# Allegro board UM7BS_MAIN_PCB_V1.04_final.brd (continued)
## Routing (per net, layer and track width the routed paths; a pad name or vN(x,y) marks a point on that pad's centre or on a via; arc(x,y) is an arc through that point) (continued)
GND_EARTH:
  vias: v1(81,12.24) v1(82.24,13.21) v1(83.39,14.42) v1(86.83,14.37) v1(89.73,14.75) v1(91.16,18.72) v1(91.16,16.16) v1(93.09,30.7) v1(94.33,18.52) v1(97.19,30.48) v1(97.26,25.74) v1(97.87,30.48) v1(97.92,22.71) v1(97.89,19.92) v1(98.06,17.3) v1(99.57,21.39) v1(100.41,41.04) v1(100.39,38.61) v1(100.44,36.29) v1(100.49,33.51) v2(81.7,22.25) v2(81.7,21.36) v2(81.7,20.47) v2(96.48,30.22) v2(96.48,28.66)
PGNDSNS1: length 13.7
  TOP w0.203: U11.36 165.7,20.39 v1(165.74,20.35)
  TOP w0.254: R837.1 175.15,24.09 174.46,23.4 173.95,23.4 v1(173.67,23.68)
  LAY4 w0.254: v1(173.67,23.68) 173.53,23.82 171.07,23.82 170.4,24.49 168.7,24.49 165.74,21.53 v1(165.74,20.35)
PGNDSNS6: length 37.1
  TOP w0.178: v1(164.29,21.99) 164.29,21.99 U11.40
  LAY3 w0.305: v1(192.83,23.21) 190.62,23.21 189.83,22.42 172.98,22.42 170.5,24.9 168.27,24.9 165.86,22.48 164.79,22.48 v1(164.29,21.99)
  BOTTOM w0.508: v1(192.83,23.21) 194.65,23.21 196.72,21.14 R838.1
V1P24A_PWRGD: length 43
  LAY4 w0.102: v1(157.89,51.28) 158.26,51.65 164.04,51.65 165.99,49.7 169.38,49.7 170.09,48.99 170.09,44.95 165.6,40.45 163,40.45 162.2,39.66 162.2,32.45 v1(163.06,31.59)
  BOTTOM w0.102: v1(163.06,31.59) 163.43,31.21 R559.2 ; R3105.2 155.12,50.38 155.58,50.83 157.44,50.83 v1(157.89,51.28)
  BOTTOM w0.203: R3105.2 154.76,50.38 154.56,50.58 154.56,51.57 154.37,51.76 U53.5
VBAT: length 4.5
  BOTTOM w0.114: U31.3 62.43,69.46 63.02,70.04 63.02,70.79 63.94,71.71 R387.2 R385.2
VCC0_SENSEP_R: length 12.4
  TOP w0.254: U1.AG32 184.83,64.88 v1(184.45,65.26)
  LAY3 w0.102: v1(184.45,65.26) 184.83,64.88 184.83,62.7
  LAY3 w0.203: 184.83,62.7 185.03,62.5 186.59,62.5 187.41,61.67 188.3,61.67 189.77,60.2 191.55,60.2 v1(192.04,60.7)
  BOTTOM w0.203: R101.1 192.12,60.77 v1(192.04,60.7)
VCC1_SENSEP_R: length 1.4
  TOP w0.203: v1(183.67,63) 183.3,63.37 U1.AD29
  BOTTOM w0.203: v1(183.67,63) 183.52,62.85 R103.1
VCC1_USB3.0: length 4.7
  TOP w0.635: J4.1 v2(11.95,92.82)
  BOTTOM w0.305: R472.2 17.59,87.11 15.09,87.11
VCC2_USB3.0: length 3.5
  TOP w0.762: v2(38.86,92.15) 38.85,92.16 CN18.1
  BOTTOM w0.305: R479.2 46.17,88.93
VCC_8625: length 72.8
  TOP w0.305: v1(159.96,90.77) 160.55,91.35 160.55,98.91 158.19,101.27 152.01,101.27 151.32,100.59 151.32,99.85 150.55,99.08 147.55,99.08 144.8,96.32 R269.2 141.18,96.33 U17.8 141.18,99.17 140.91,99.44 139.71,99.44 139.34,99.07 ; 139.34,99.07 138.95,99.46 137.01,99.46 136.4,98.85 136.4,96.54 R271.2 ; 139.34,99.07 R270.2 ; v1(151.11,86.23) 151.44,86.57 151.44,88.41 151.99,88.96 152.95,88.96 153.48,88.43 153.48,87.31 154.57,86.22 v1(155.08,86.22)
  TOP w0.508: v1(159.96,90.77) 155.41,86.22 v1(155.08,86.22)
  BOTTOM w0.203: U16.13 156.51,93.97 156.73,93.75 156.73,93.3 156.55,93.3 156.28,93.57 U16.14
  BOTTOM w0.305: R276.1 151.7,86.23 v1(151.11,86.23) 151.11,86.23 U18.8 ; R277.1 v1(155.08,86.22)
  BOTTOM w0.508: v1(159.96,90.77) 159.87,90.86 158.35,90.86 157.86,91.35 C308.1 157.48,91.71 156.82,92.36 156.82,93.21 156.73,93.3
  BOTTOM w0.762: FB38.2 161.51,88.92 FB6.1 160.05,90.68 v1(159.96,90.77)
VCC_LX: length 11.1
  TOP w0.178: 165.58,19.39 165.39,19.59 U11.34
  TOP w0.305: 165.58,19.39 165.88,19.1
  TOP w0.508: 165.88,19.1 167.67,17.3
  TOP w0.635: 167.67,17.3 C223.1 170.65,17.3 172.79,19.44 174.22,19.44
VCC_SENSEP: length 35.1
  LAY3 w0.203: v1(184.45,62.99) 184.45,62.46 184.87,62.04 186.54,62.04 187.29,61.29 188.24,61.29 189.53,60 189.53,59.35 189.93,58.94 192.73,58.94 v1(193.46,59.67) 193.94,59.2 194.47,59.2 194.88,58.79 194.88,57.54 195.61,56.81 195.61,54.38 196.75,53.25 196.75,47.14 197.26,46.63 197.26,42.24 v1(196.25,41.23)
  BOTTOM w0.203: v1(193.46,59.67) 193.63,59.84 R101.2 ; v1(196.25,41.23) 196.11,41.1 R563.2 ; R103.2 184.47,62.97 v1(184.45,62.99)
VCC_USB2: length 6.6
  TOP w0.203: F4.2 44.11,19.64 44.11,24.26 R484.2
VCC_USB3: length 3.5
  TOP w0.203: 63.08,17.03 62.67,17.44 R490.2
VDD10: length 25.3
  LAY4 w0.508: v1(119.15,34.54) 118.3,35.39 116.9,35.39 v1(114.78,37.51)
  BOTTOM w0.178: U22.29 125.03,39.2 v1(125.25,38.98) ; U22.9 115.36,39.6 ; U22.45 119.93,34.81 119.66,34.54 v1(119.15,34.54) ; 115.05,36.95 116.99,36.95 117.24,37.2 U22.3 ; C344.1 115.05,38.22 116.36,38.22 116.54,38.4 U22.6 ; v1(122.33,34.54) 121.53,35.34 U22.41 ; 118.53,42.02 118.73,41.82 U22.13
  BOTTOM w0.381: C343.1 v1(125.25,38.98) ; C345.1 122.45,34.41 v1(122.33,34.54) ; v1(116.4,43.07) 116.51,43.18 C342.1 116.9,42.53 117.41,42.02 118.53,42.02 ; C341.1 118.64,34.03 v1(119.15,34.54)
  vias: v1(123.13,46.87) v1(123.67,46.88) v1(127.46,30.93) v1(127.97,30.92)
VDD12: length 12.9
  TOP w0.406: FB5.2 158.02,90.45 v1(155.38,87.81)
  BOTTOM w0.203: U16.19 153.51,92.32
  BOTTOM w0.305: C309.1 154.11,87.78 153.53,88.37 153.53,89.52 154.01,90 C311.2 C310.2 154.01,91.82 153.51,92.32
VDD18: length 1.2
  BOTTOM w0.203: U95.18 71.14,95.87 C706.2
VDD33: length 18.8
  BOTTOM w0.178: v1(123.34,34.54) 123.26,34.62 123.01,34.62 122.33,35.3 U22.39 ; U22.12 117.21,40.8 v1(116.87,41.14) ; U22.42 121.13,34.97 v1(121.56,34.54) ; v1(125.25,40) U22.27
  BOTTOM w0.305: 115.81,46.3 116.28,46.76 Q35.1
  BOTTOM w0.381: v1(125.25,40) 125.25,40 C327.1 ; C329.1 v1(123.34,34.54) ; C331.1 v1(121.56,34.54) ; 115.81,46.3 C328.1 116.3,41.7 v1(116.87,41.14) ; R317.1 124.23,32.63 123.85,32.25 v1(123.34,32.25)
  BOTTOM w0.508: v1(130.16,37.86) 130.58,38.28 R302.1 ; R299.2 v1(130.58,34.83)
  vias: v1(117.63,34.67)
VDDIO_8625: length 16.2
  TOP w0.305: v1(148.27,97.17) 148.23,97.13 R272.2
  LAY3 w0.305: v1(161.22,92.02) 160.98,92.25 154.01,92.25 v1(153.43,91.67)
  BOTTOM w0.203: C304.2 147.66,97.17 v1(148.27,97.17) U16.38 ; R262.2 R263.2 161.41,92.22 v1(161.22,92.02) ; U16.50 v1(152.71,100.33) 152.72,100.34 C295.2
  BOTTOM w0.305: R274.2 v1(151.37,89.65) 151.65,89.38 R273.2
VDDQ_LX: length 34.3
  TOP w0.178: U11.42 165.65,22.79 165.84,22.6 166.47,22.6
  TOP w0.381: 167.35,23.04 166.9,22.6 166.47,22.6
  TOP w0.635: 167.35,23.04 C213.1 168.07,23.04 v2(169.24,21.88)
  LAY3 w0.635: v2(195.34,20.8) 195.34,19.83 193.7,18.19 183.96,18.19 183.24,18.9 172.21,18.9 v2(169.24,21.88)
VDDRX: length 4.6
  TOP w0.406: FB5.1 158.02,95.93 C305.2 C306.2 157.36,96.76 v1(157.35,96.77)
  BOTTOM w0.203: U16.6 156.86,96.77
  BOTTOM w0.406: C307.2 157.98,96.77 v1(157.35,96.77) 156.86,96.77
VIN_LCD: length 23.1
  TOP w0.508: 137.19,89.46 136.48,89.46 135.1,88.07 128.36,88.07 128.02,88.41 126.69,88.41 v1(126.64,88.36) 126.35,88.07 v1(120.31,88.07)
  BOTTOM w0.305: v1(120.31,88.07) 119.95,87.71 119.95,86.51 119.65,86.2 U41.13
  BOTTOM w0.406: v1(126.64,88.36) 126.93,88.08 126.93,87.57 127.28,87.21 R3089.2 127.28,86.22 R3090.2
5A_ONOFF: length 120.2
  TOP w0.203: v1(86.44,76.17) 86.34,76.08 72.71,76.08 72.21,76.57 v1(60.66,76.57)
  LAY3 w0.203: v1(116.9,79.4) 116.48,78.97 109.29,78.97 107.27,76.95 103.04,76.95 101.79,75.71 86.9,75.71 v1(86.44,76.17)
  LAY4 w0.102: v1(48.63,77.02) 48.66,76.98 60.25,76.98 v1(60.66,76.57)
  LAY4 w0.203: v1(115.42,60.46) 115.42,73.28 117.22,75.08 117.22,79.08 v1(116.9,79.4)
  BOTTOM w0.114: v1(48.63,77.02) 48.63,76.87 49.94,75.56 R403.2
  BOTTOM w0.203: U10.6 119.46,60.96 119.24,60.74 ; U10.20 122.76,60.96 123.05,60.67 ; v1(60.66,76.57) 60.66,77.06 60.36,77.36 R444.2
  BOTTOM w0.305: R601.1 R600.1 R186.2 118.96,60.46 119.24,60.74
  BOTTOM w0.406: R601.1 v1(115.42,60.46) 115.3,60.34 115.3,57.09 116.28,56.11 125.06,56.11 125.91,56.96 125.91,59.47 R185.1 125.77,59.99 123.73,59.99 123.05,60.67
8625_PD#: length 6.6
  BOTTOM w0.152: U16.10 156.32,95.17 157.28,94.21 157.28,93.07 157.49,92.85 C301.2 157.86,92.64 158.11,92.4 160.19,92.4 R263.1
8625_PWMO: length 43
  LAY3 w0.102: v1(155.12,93.88) 154.61,94.39 149.96,94.39 148.89,95.47 119.36,95.47 117.01,93.12 v1(117.01,93.08)
  BOTTOM w0.152: U16.12 155.38,94.37 155.12,94.12 v1(155.12,93.88)
  BOTTOM w0.203: R528.2 117.01,91.12 v1(117.01,93.08)
8625_RST#: length 5.9
  BOTTOM w0.152: R262.1 160.09,93.3 158.2,93.3 157.9,93.6 C300.2 157.9,94.02 156.35,95.57 U16.9
+V_ADP_IN:
  vias: v2(138.73,22.73)
+V_DC: length 12.9
  BOTTOM w0.203: U10.12 120.8,64.45 C176.2
  BOTTOM w0.508: C176.2 119.63,65.62 119.63,69.86 v1(120.46,70.7) ; R497.2 v1(142.01,27.56)
  BOTTOM w0.635: R194.1 v1(147.39,18.22)
  vias: v2(141.58,59.21) v2(141.58,58.45) v2(141.74,48.79) v2(141.74,48) v2(141.74,47.22) v2(142.36,59.21) v2(142.36,58.45) v2(142.5,48.79) v2(142.5,48) v2(142.5,47.22) v2(143.15,59.21) v2(143.15,58.45)
+V_LED:
  vias: v2(119.05,97.37)
+VCORE: length 11.5
  TOP w0.203: U1.AJ27 185.64,62.61 v1(186.02,62.99) ; v1(186.02,63.75) 185.64,63.37 U1.AJ29 ; U1.AG29 184.86,63.37 v1(185.24,63.75) ; v1(185.24,62.99) 184.86,62.61 U1.AG27 ; v1(186.02,64.5) 185.64,64.12 U1.AJ30 ; U1.AF30 184.07,64.12 v1(184.45,64.5) ; U1.AF29 184.07,63.37 v1(184.45,63.75) ; v1(185.24,64.5) 184.86,64.12 U1.AG30
  BOTTOM w0.203: v2(195.6,44.98) 194.85,44.24 194.85,41.39 195.34,40.91 R823.2
  BOTTOM w0.381: C34.1 186.47,62.16 186.02,62.6 v1(186.02,62.99)
  BOTTOM w0.762: C40.1 v2(195.57,44.19)
  vias: v1(184.45,68.26) v1(184.45,67.54) v1(184.45,66.78) v1(185.23,68.26) v1(185.24,67.54) v2(191.85,40.37) v2(193.06,40.07) v2(195.57,46.28) v2(196.42,46.26) v2(196.46,45.03) v2(196.48,44.21)
+VEC_LDO: length 126.2
  TOP w0.178: v1(155.88,22.03) 155.93,21.99 U11.9
  LAY3 w0.381: v1(135.01,79.62) 126.06,79.62 125.1,78.66 118.85,78.66 117.54,79.98 115.98,79.98 115.4,79.4 107.19,79.4 105.34,77.55 103.01,77.55 101.76,76.3 87.75,76.3 87.05,77 v1(84.52,77)
  LAY4 w0.381: v1(155.88,22.03) 155.8,21.95 151.23,21.95 150.16,23.02 150.16,47.12 147.24,50.04 147.24,57.48 143.94,60.78 142.93,60.78 137.95,65.76 137.95,76.68 v1(135.01,79.62)
  BOTTOM w0.508: C221.2 156.83,22.03 v1(155.88,22.03) ; D31.P v1(84.52,77)
+VGG: length 27.6
  TOP w0.254: U1.AD16 U1.AF16 184.07,57.3 v1(184.45,57.68) ; U1.AK24 186.4,61.09 v1(186.02,60.71) ; v1(184.45,57.68) 184.83,58.06 U1.AG18 ; v1(184.45,57.68) 184.83,57.3 U1.AG16 ; v1(185.24,60.71) 185.62,61.09 U1.AJ24 ; U1.AD18 U1.AF18 184.07,58.06 v1(184.45,58.44) 184.83,58.82 U1.AG19 ; v1(184.45,60.71) 184.83,61.09 U1.AG24 ; v1(184.45,59.95) 184.83,60.33 U1.AG22 ; U1.AJ19 185.62,58.82 v1(185.24,59.2) 185.62,59.57 U1.AJ21 ; U1.AG21 184.83,59.57 v1(184.45,59.2) 184.07,58.82 U1.AF19 ; U1.AD19 183.29,58.82 v1(183.67,59.2) 184.05,59.57 U1.AF21 ; U1.AJ22 185.62,60.33 v1(185.24,59.95) ; U1.AF22 184.05,60.33 v1(183.67,59.95)
  TOP w0.305: R825.2 155.69,31.14 155.91,31.36 162.01,31.36 162.26,31.1 164.69,31.1 165.79,30 170.08,30 170.41,30.33 170.41,31.18
  vias: v1(172.08,34.55) v1(172.12,33.28) v1(173.37,33.96) v1(174.54,33.95) v1(176.77,38.83) v1(176.76,38.33) v1(178.08,38.01) v1(182.97,40.2) v2(172.14,33.9) v2(175.16,37.99) v2(175.7,37.49) v2(178.67,39.68) v2(178.69,38.93) v2(178.71,38.18) v2(182.51,43.03) v2(182.54,42.23) v2(182.51,41.52) v2(182.51,40.76) v2(183.41,43) v2(183.43,42.27) v2(183.45,41.5) v2(183.45,40.74)
+VNN: length 14.6
  TOP w0.254: U1.AA21 181.72,59.57 v1(182.1,59.95) 182.48,60.33 U1.AC22 ; v1(182.1,61.47) 182.48,61.85 U1.AC25 ; v1(182.1,61.47) 181.72,61.85 U1.AA25 ; v1(182.1,61.47) 181.72,61.09 U1.AA24 ; U1.AA18 181.72,58.06 v1(182.1,58.44) 182.48,58.82 U1.AC19 ; U1.AC18 182.48,58.06 v1(182.1,57.68) ; U1.AD27 183.41,62.48 183.41,61.98 U1.AD25 182.9,61.47 v1(182.88,61.47) ; U1.AC24 182.48,61.09 v1(182.1,60.71) 181.72,60.33 U1.AA22 ; U1.AC21 182.48,59.57 v1(182.1,59.2) 181.72,58.82 U1.AA19
  BOTTOM w0.381: v1(182.88,61.47) v1(182.1,61.47) 182.25,61.63 C27.2 ; R821.2 165.69,39.92 164.9,39.13 ; C28.2 183.31,56.93 182.8,57.44 C25.2 182.14,57.72 v1(182.1,57.68) ; C26.2 182.27,58.61 v1(182.1,58.44)
  vias: v2(151.03,27.38) v2(151.03,26.58) v2(151.03,25.79) v2(151.03,25.02) v2(163.85,38.59) v2(163.85,37.83) v2(164.68,38.59) v2(164.68,37.83)
+VSDIO: length 1.5
  TOP w0.254: U1.E1 173.5,50.25 U1.E2
  TOP w0.406: U1.E1 173.5,49.44 v1(173.12,49.07)
+VSM: length 161.9
  TOP w0.178: U11.44 165.95,23.59 v1(165.97,23.57)
  TOP w0.203: U11.46 165.4,24.39 165.46,24.45 166.09,24.45 166.24,24.6
  TOP w0.254: v1(196.18,74.11) 195.67,73.6 U1.BJ49 195.44,73.65 U1.BH49 194.89,74.22 U1.BH50 194.89,74.25 U1.BG51 194.31,74.25 U1.BE51 192.69,74.25 v1(192.55,74.11) ; U1.AV10 190.12,54.28 v1(190.52,54.68) ; U1.AV16 190.29,57.19 v1(190.64,56.83) ; U1.AM18 187.21,58.06 v1(187.59,57.68) 187.97,58.06 U1.AN18 ; U1.BE3 v1(192.7,50.96) ; v1(194.33,51.5) 194.4,51.57 U1.BH5 194.89,50.99 U1.BH4 194.89,50.96 U1.BG3 v1(193.77,50.96) ; U1.BE1 v1(193.66,49.21) ; v1(191.41,54.68) 191.01,54.28 U1.AY10 ; U1.BJ2 v1(196.1,50.22) ; U1.AY44 190.89,70.94 v1(190.52,71.31) 190.37,71.31 U1.AV44 ; U1.AM25 187.21,61.85 v1(187.59,62.23) ; v1(190.01,57.72) 189.57,58.16 U1.AU18 ; v1(194.71,76.77) 194.45,76.77 194,76.32 194,75.86 193.66,75.52 U1.BE53 ; U1.AN36 187.97,67.16 v1(187.59,67.54) ; U1.AU36 v1(189.99,67.39) 189.99,67.65 U1.AV38 ; U1.BJ5 v1(196.11,51.62) ; U1.BJ3 v1(196.07,50.83) ; U1.BJ51 U1.BJ52 195.74,75.25 v1(196.49,75.25) ; U1.AM36 187.18,67.16 v1(186.8,67.54) ; v1(187.59,58.44) 187.97,58.82 U1.AN19 ; v1(187.59,66.78) 187.97,66.4 U1.AN35 ; U1.AN27 187.98,62.55 v1(188.38,62.14)
  TOP w0.305: CN1.106 v1(221.35,67.45) ; CN1.82 v1(221.35,74.65) ; CN1.111 210,65.95 ; CN1.88 v1(221.35,72.85) ; CN1.94 v1(221.35,71.05) ; CN1.124 221.13,62.05 v1(221.38,62.3) ; CN1.99 210,69.55 ; CN1.100 v1(221.35,69.25) ; CN1.118 v1(221.35,63.85) ; CN1.81 210,74.95 ; CN1.105 210,67.75 ; CN1.75 210,76.75 ; CN1.93 210,71.35 ; CN1.123 210,62.35 ; CN1.87 210,73.15 ; CN1.112 v1(221.35,65.65) ; CN1.117 210,64.15 ; CN1.76 v1(221.35,76.45)
  TOP w0.508: 209.69,76.65 209.69,93.18 209.13,93.75 R148.2
  LAY4 w0.254: v1(165.97,23.57) 165.97,24.28 167.38,25.69 168.16,25.69 172.66,30.19 187.23,30.19 190.55,33.51 198.61,33.51 201.25,36.15
  LAY4 w1.016: 201.97,35.48 191.85,25.36 180.65,25.36 180.15,25.86 172.71,25.86 v2(171.63,24.78)
  BOTTOM w0.203: v2(171.63,24.78) 170.97,24.12 170.97,19.8 168.13,16.96 R9.1
  BOTTOM w0.381: R214.1 195.46,34.42 v1(195.98,34.93)
  vias: v1(208.3,75.5) v1(208.93,75.5) v2(201.06,54.55) v2(201.06,51.25) v2(201.59,38.7) v2(202.64,38.72) v2(203.09,51.25) v2(204.27,38.49) v2(205,46.29) v2(205,43.5) v2(205.44,40.13) v2(205.48,38.57) v2(206.74,38.55)
+VSM_VTT: length 113.8
  TOP w0.178: U11.48 165.18,25.19 165.35,25.36 165.35,25.97 ; U11.47 165.54,24.79 165.86,25.11
  TOP w0.254: v1(174.27,23.87) 174.35,23.95 174.35,25.28 172.91,26.72 172.91,28.05 172.59,28.36 171.73,28.36 170.8,29.29 167.52,29.29 167.23,29 167.23,27.36 166.89,27.02 166.4,27.02 165.35,25.97
  LAY4 w0.381: v1(218.32,37.87) 215.19,37.87 214.17,36.85 214.17,35.3 209.08,30.2 201.87,30.2 194.19,22.52 190.74,22.52 190.27,22.05 175.57,22.05 174.27,23.35 v1(174.27,23.87)
  LAY4 w1.016: v1(210.2,38.29) 210.2,36.25 206.39,32.43 201.45,32.43 193.21,24.19 179.98,24.19 179.45,24.72 v2(173.58,24.72)
  vias: v1(213.38,38.17)
A6: length 72.5
  TOP w0.102: 170.48,52.16 169.14,53.5 168.43,53.5 167.98,53.95 v1(167.98,54.12)
  TOP w0.114: U1.A6 170.48,52.16
  LAY4 w0.102: v1(167.98,54.12) 168.94,55.08 168.94,58.44 168.02,59.35 168.02,61.48 168.45,61.91 168.45,71.74 170.19,73.48 170.19,78.57 172.73,81.11 177.04,81.11 179.3,78.85 182.85,78.85 189.78,85.78 189.78,92.31 v1(185.31,96.78)
  BOTTOM w0.102: U7.2 182.67,98.02 R144.1 183.92,96.78 v1(185.31,96.78)
A_EARPHONE_SEL: length 13.1
  BOTTOM w0.254: J3.6 35.04,23.73 35.46,23.31 R355.1 35.46,22.36 35.19,22.09 30.37,22.09 28.69,23.77 28.69,25.04 27.97,25.76 R339.1
AC_PRESENT: length 140
  LAY3 w0.102: v1(75,75.6) 75.4,76 84.4,76 85.77,74.63 101.12,74.63 103.04,76.55 107.6,76.55 109.02,77.96 153.81,77.96 v1(153.82,77.98)
  LAY4 w0.102: v1(163.67,60.73) 163.24,60.73 162.27,59.75 159.39,59.75 159.07,60.08 159.07,61.93 153.82,67.18 v1(153.82,77.98) ; v1(46.49,76.51) 46.49,76.87 48.4,78.78 71.82,78.78 v1(75,75.6)
  BOTTOM w0.102: R398.2 46.51,76.49 v1(46.49,76.51) ; Q8.1 164.32,60.08 v1(163.67,60.73)
AC_VREF: length 3.6
  BOTTOM w0.178: U25.28 21.3,33.84 21.09,33.63 20.82,33.63 20.09,32.9
  BOTTOM w0.305: 20.09,32.9 C365.2 19.78,33.75 C363.1
ADP_IN#: length 2.7
  BOTTOM w0.102: U31.71 45.74,60.26 44.55,59.07 R453.2
AUD_MIC1_IN_L: length 9.3
  BOTTOM w0.305: R337.1 23.69,26.49 R336.2 22.9,22.32 25.34,19.88 R348.2
AUD_MIC1_IN_R: length 24.4
  BOTTOM w0.305: R347.2 34.02,17 32.52,15.5 27.74,15.5 21.24,22 21.24,26.5 ; R334.2 21.24,26.5 ; 21.24,26.5 R335.1
AUD_MIC_IN_L: length 2
  BOTTOM w0.178: C377.2 25.43,30.35 U25.17
AUD_MIC_IN_R: length 2.1
  BOTTOM w0.178: U25.18 25.03,30.66 C373.2
AUDIO_DVDD_IO: length 0.8
  BOTTOM w0.178: U25.9 28.49,33.84
AUXN_LVDS: length 3
  BOTTOM w0.124: U16.1 156.47,98.77 156.54,98.69 156.76,98.69 156.99,98.92 156.99,99.45 157.34,99.8 157.74,99.8 C299.1
AUXP_LVDS: length 3
  BOTTOM w0.124: U16.2 156.47,98.37 156.54,98.44 156.87,98.44 157.24,98.81 157.24,99.35 157.44,99.55 157.74,99.55 C303.1
AXGND: length 17.7
  TOP w0.178: U11.52 162.84,26.91 v1(162.94,27.01)
  TOP w0.381: v1(162.94,27.01) 162.94,29.3 ; C193.1 v1(163.7,28.59) ; C243.1 165.19,14.6 v1(165.02,14.43) ; R195.1 157.3,29.8 157.64,30.14 159.17,30.14 C182.1
  TOP w0.406: C243.1 164.23,15.41 R211.2
  LAY4 w0.305: v1(165.02,14.43) 164.51,14.43 164.02,13.94 160.39,13.94 160.17,14.16 158.99,14.16 158.08,15.06 156.93,15.06 v1(156.67,14.81)
  vias: v1(162.21,30.08)
BH53: length 34.6
  TOP w0.102: U1.BH53 195.43,75.42 197.09,77.08 197.09,80.33 196.8,80.62 R596.1 196.65,87.47 v1(187.41,96.7)
  BOTTOM w0.102: U7.1 182.86,98.67 R143.1 182.86,99.51 183.23,99.88 184.23,99.88 v1(187.41,96.7)
BL_ADJ: length 152.2
  TOP w0.203: v1(105.7,98.75) 105.7,90.52 v1(105.64,90.47) ; v1(147.33,100.07) 147.66,100.39 R260.1
  LAY3 w0.102: v1(59.23,85.54) 59.23,84.86 54.31,79.93 54.31,75.41 56.17,73.55 56.17,61.73 57.22,60.68 v1(57.34,60.68)
  LAY3 w0.203: v1(84.07,97.29) 101.8,97.29 103.27,98.75 v1(105.7,98.75) 107.21,100.26 135.07,100.26 135.35,99.98 144.74,99.98 145.35,100.59 146.81,100.59 v1(147.33,100.07)
  LAY4 w0.203: v1(59.23,85.54) 61.42,87.73 74.51,87.73 v1(84.07,97.29)
  BOTTOM w0.203: U31.25 57.36,60.66 v1(57.34,60.68) ; v1(105.64,90.47) 105.64,91.57 105.85,91.78 110.82,91.78 111.08,92.04 115.04,92.04 115.84,91.24 115.84,89.82 116.23,89.43 R530.1
BLCTL_EC: length 135.3
  LAY3 w0.102: v1(58.49,81.97) 59.07,82.55 60.62,82.55 62.93,80.24 87.19,80.24 89.45,77.99 99.5,77.99 101.88,80.36 103.39,80.36 105.29,82.27 115.6,82.27 115.98,81.89 121.59,81.89 123.16,80.32 143.87,80.32 v1(144.36,79.83) ; v1(56.48,82.97) 56.38,82.97 53.38,79.98 53.38,72.31 52.99,71.92 52.99,53.35 v1(53.6,52.74)
  BOTTOM w0.102: v1(144.36,79.83) 144.36,81.79 146.86,84.3 R542.2 ; v1(58.49,81.97) 57.49,82.97 v1(56.48,82.97) ; v1(53.6,52.74) 53.6,53.1 R443.1 R439.2
  BOTTOM w0.203: R542.2 146.57,86.36 U42.2
BT_ON: length 247.7
  LAY3 w0.102: v1(60.28,31.81) 62.84,34.37 v1(62.84,56.16)
  LAY4 w0.102: v1(234.03,15.55) 232.5,17.09 227.12,17.09 219.99,9.96 181.97,9.96 179.77,12.16 173.91,12.16 172,10.25 153.76,10.25 150.72,13.29 146.12,13.29 143.61,10.78 140.98,10.78 140.55,11.21 130.5,11.21 127.23,14.48 109.98,14.48 105.6,18.87 105.6,45.5 104,47.1 98.24,47.1 88.16,37.02 73.36,37.02 68.16,31.81 v1(60.28,31.81)
  BOTTOM w0.102: v1(234.03,15.55) 234.01,15.53 R790.2
  BOTTOM w0.114: U31.30 62.52,58.66 62.84,58.34 v1(62.84,56.16)
BT_RF_KILL_R*: length 2.7
  TOP w0.102: CN26.54 v1(231.78,15.52)
  BOTTOM w0.102: v1(231.78,15.52) 232.5,15.52 R790.1 R789.2
BUF_PLT_RST#: length 261.5
  TOP w0.152: v1(54.14,44.5) 56.93,47.29 56.93,49.63 66.15,58.85 v1(67.07,58.85)
  LAY3 w0.152: v1(145.33,11.53) 142.41,11.53 140.93,13.01 126.52,13.01 v1(120.65,18.89)
  LAY4 w0.152: v1(120.65,18.89) 120.65,22.99 126.99,29.34 128.67,29.34 133.48,34.15 133.48,40.3 130.49,43.28 v1(126.87,43.28) 126.56,42.97 118.4,42.97 116.21,45.15 112.84,45.15 108.11,49.88 97.61,49.88 96.03,51.46 96.03,58.44 92.69,61.78 82.5,61.78 79.96,59.24 74.03,59.24 v1(72.96,60.31) 72.58,60.69 68.91,60.69 v1(67.07,58.85) ; v1(226.72,16.08) 220.37,9.72 181.35,9.72 179.18,11.89 174.15,11.89 172.27,10.01 153.66,10.01 151.2,12.46 146.26,12.46 v1(145.33,11.53)
  BOTTOM w0.114: v1(67.07,58.85) 67.07,59.16 65.43,60.81 65.43,61.44 R428.2 ; R126.1 75.75,59.24 76.37,58.63 U6.10 ; v1(126.87,43.28) 126.87,43.27 R306.2
  BOTTOM w0.152: U27.2 227.91,16.8 227.56,16.45 R372.2 v1(226.72,16.08) ; CN11.4 52.46,43.84 53.12,44.5 v1(54.14,44.5) ; v1(72.96,60.31) 73.5,59.77 75.08,59.77 75.27,59.58 R126.1
CLK: length 42.6
  TOP w0.114: U11.58 160.44,26.48 160.1,26.81 v1(160.1,27.04)
  LAY4 w0.127: v1(160.1,27.04) 160.28,27.22 160.82,27.22 162.82,25.22 164.95,25.22 166.74,27 166.74,28.72 168.27,30.25 170.67,30.25 173.36,32.95 180.48,32.95 180.86,33.33 185.45,33.33 v1(188.96,36.84)
  BOTTOM w0.114: v1(188.96,36.84) 188.7,37.09 R570.2
CLK_LAN_OE#: length 133.7
  TOP w0.089: U1.AM10 186.94,54.28 v1(186.58,53.91)
  LAY3 w0.102: v1(201.19,28.38) 196.97,28.38 191.12,34.23 175.13,34.23 170.67,38.69 170.67,40.24 164.78,46.13 158.91,46.13 157.91,45.13 154.16,45.13 153.79,44.76 150.98,44.76 150.7,45.03 146.36,45.03 145.35,44.02 145.35,41.49 144.97,41.11 143.65,41.11 141.74,43.02 131.32,43.02 130.62,43.72 122.51,43.72 119.32,46.91 v1(118.26,46.91)
  BOTTOM w0.102: R27.1 192.12,46.39 192.4,46.1 192.4,39.39 201.19,30.61 v1(201.19,28.38) ; v1(118.26,46.91) 118.61,47.26 R308.1 119.35,47.95 118.99,48.31 Q35.2
  BOTTOM w0.114: v1(186.58,53.91) 187.49,53 187.49,52.82 188.24,52.07 189.31,52.07 190.01,51.37 190.01,50.87 191.03,49.85 191.03,48.71 191.79,47.94 R27.1
CLK_PCIE_LAN_N: length 66.1
  TOP w0.102: 171.63,59.98 172.01,59.98 172.3,59.69 U1.C21
  TOP w0.109: 171.63,59.98 169.96,59.98 169.88,59.9 167.18,59.9 166.97,60.1 165.71,60.1 v1(165.52,60.29)
  LAY3 w0.104: v1(165.52,60.29) 165.51,60.3 163.21,60.3 159.33,56.43 159.33,55.07 154.35,50.09 136.47,50.09 133.56,47.19 130.47,47.19 130.1,47.55 130.1,47.91 v1(130.33,48.14)
  BOTTOM w0.109: U22.20 121.53,42.05 121.44,42.14 121.44,47.36 121.92,47.84 126.6,47.84 127.41,47.03 130.01,47.03 130.33,47.35 v1(130.33,48.14)
CLK_PCIE_LAN_P: length 66.1
  TOP w0.102: 171.63,59.74 171.64,59.75 171.8,59.75
  TOP w0.109: U1.A21 171.8,59.75 ; v1(165.52,59.68) 165.71,59.87 166.87,59.87 167.08,59.66 169.98,59.66 170.06,59.74 171.63,59.74
  LAY3 w0.104: v1(165.52,59.68) 165.16,60.05 163.31,60.05 159.59,56.32 159.59,54.97 154.46,49.84 136.57,49.84 133.67,46.93 130.36,46.93 129.85,47.44 129.85,47.85 v1(129.56,48.14)
  BOTTOM w0.109: U22.19 121.13,42.05 121.21,42.13 121.21,47.46 121.82,48.07 126.7,48.07 127.51,47.26 129.91,47.26 130.1,47.45 130.1,47.67 129.62,48.14 v1(129.56,48.14)
CLK_PCIE_WLAN_N: length 212
  TOP w0.101: 169.71,59.04 169.72,59.03 170.64,59.03 170.94,59.33 172.11,59.33 U1.B20
  TOP w0.109: v1(165.35,98.72) 165.35,98.52 165.24,98.41 164.96,98.41 164.85,98.3 164.85,94.15 159.61,88.92 159.61,64.1 164.68,59.04 169.71,59.04 ; CN26.49 238.89,16.77 239.15,17.04 239.41,17.04 241.73,19.36 241.73,21.13 243.53,22.93 243.53,23.46 243.25,23.74 243.25,24.27 243.1,24.42 v1(242.84,24.42)
  LAY3 w0.104: v1(242.84,24.42) 243.2,24.07 243.36,24.07 243.49,24.2 243.49,34.38 229.24,48.63 229.24,92.42 217.27,104.39 212.57,104.39 208.84,100.66 192.25,100.66 191.38,101.53 165.18,101.53 164.86,101.21 164.86,99.2 v1(165.35,98.72)
CLK_PCIE_WLAN_P: length 212
  TOP w0.101: 169.71,58.8 169.74,58.8 169.74,58.8 170.73,58.8 171.03,59.1 171.91,59.1 172.29,58.72 U1.C19
  TOP w0.109: v1(242.84,23.81) 243.29,23.36 243.29,23.03 241.49,21.23 241.49,19.45 239.31,17.27 CN26.47 ; 169.71,58.8 164.58,58.8 159.38,64 159.38,89.02 164.61,94.25 v1(164.61,98.72)
  LAY3 w0.104: v1(164.61,98.72) 164.61,101.32 165.07,101.78 191.49,101.78 192.36,100.91 208.73,100.91 212.47,104.64 217.38,104.64 229.49,92.52 229.49,48.73 243.74,34.48 243.74,24.09 243.46,23.81 v1(242.84,23.81)
CLK_WLAN_OE#: length 86
  TOP w0.089: v1(186.58,54.68) 186.77,54.68 U1.AM12
  LAY4 w0.102: v1(234.48,26.35) 201.38,26.35 v1(201.12,26.61)
  BOTTOM w0.102: Q41.2 235.78,11.75 234.48,13.04 v1(234.48,26.35) ; v1(201.12,26.61) 201.6,27.1 201.6,30.54 194.22,37.93 194.22,43.09 193.84,43.47 R26.1
  BOTTOM w0.114: R26.1 192.7,44.08 192.7,46.19 192.27,46.62 192.27,48.36 191.53,49.09 191.53,50.1 190.96,50.68 190.96,51.39 188.92,53.43 188.92,54.07 188.31,54.68 v1(186.58,54.68)
CLK_WLAN_OE#_M2: length 2.4
  TOP w0.102: v1(236.93,15.74) 237.03,15.74 237.07,15.77 CN26.53
  BOTTOM w0.102: R786.1 237.48,15.1 236.93,15.66 v1(236.93,15.74)
CLK_WLAN_OE#_MINI: length 1.8
  BOTTOM w0.102: Q41.3 237.79,13.84 R786.2
CORE_PWROK: length 80.4
  TOP w0.102: U1.G16 174.52,56.87 v1(174.52,56.83)
  LAY3 w0.102: v1(149.44,46.02) 149.58,46.15 155.34,46.15 162.31,53.11 168.06,53.11
  LAY3 w0.127: 168.06,53.11 170.29,53.11 171.82,54.64 171.82,55.38 172.87,56.43 174.11,56.43 v1(174.52,56.83)
  LAY4 w0.102: v1(163.31,15.22) 163.2,15.22 161.91,16.51 161.91,16.61 160.37,18.15 154.84,18.15 154.15,18.84 152.99,18.84 152.14,17.99 152.14,17.31 151.35,16.52 149.96,16.52 148.91,17.56 148.91,18.83 149.2,19.12 149.2,27.49 147.21,29.48 147.21,37.67 149.44,39.91 v1(149.44,46.02)
  BOTTOM w0.102: R589.1 163.23,15.22 v1(163.31,15.22) 164.08,15.22 R587.2
DATA: length 43
  TOP w0.114: U11.59 160.04,26.49 159.58,26.94 v1(159.58,27.38)
  LAY4 w0.127: v1(159.58,27.38) 159.67,27.46 161.01,27.46 163.01,25.46 164.86,25.46 166.47,27.07 166.47,28.9 168.4,30.83 170.65,30.83 173.09,33.27 179.86,33.27 180.22,33.63 185.16,33.63 v1(188.38,36.84)
  BOTTOM w0.114: v1(188.38,36.84) 188.38,40.65 187.77,41.26 187.77,42.54 R571.2
DBG_UART1_RXD: length 4.1
  TOP w0.114: U1.T52 179.32,75.06 179.32,76.75 v1(179.85,77.28)
  BOTTOM w0.102: Q7.2 178.71,78.42 v1(179.85,77.28)
DBG_UART1_TXD: length 10.1
  TOP w0.114: v1(179.85,76.65) 180.2,76.29 180.2,75.4 179.8,75 179.68,75 179.29,74.61 U1.T51
  BOTTOM w0.089: v1(179.85,76.65) 179.21,76.65 178.39,75.83 177.68,75.83
  BOTTOM w0.102: Q6.2 175.15,76.65 175.97,75.83 177.68,75.83
DDI0_HPD: length 5
  TOP w0.102: U1.W51 180.75,74.96 180.43,75.28 180.43,76.44
  TOP w0.114: 180.43,76.44 180.43,76.82 v1(180.86,77.25)
  BOTTOM w0.114: R14.1 182.2,77.21 R2984.2 181.85,77.25 v1(180.86,77.25)
DDI1_HPD: length 10.5
  TOP w0.102: U1.R51 178.96,74.83 178.96,75.12 179.09,75.25 179.09,75.26 179.09,77.03 ; Q4.3 176.73,81.94 R18.1
  TOP w0.114: 179.09,77.03 179.09,77.92 177.82,79.19 177.35,79.19 176.07,80.46 176.07,80.7 175.41,81.36 Q4.3
DDR3_DRAM_PWROK: length 80.9
  TOP w0.102: U1.AV28 190.64,63.44 v1(190.64,63.57)
  LAY3 w0.127: v1(194.67,32.73) 194.91,32.98 194.91,35.84 198.59,39.52 198.59,40.84 198.06,41.36 198.06,46.59 198.76,47.29 198.76,56.81 194.73,60.85 194.22,60.85 192.07,62.99 191.22,62.99 v1(190.64,63.57)
  LAY4 w0.102: v1(163.36,16.41) 162.9,16.87 162.9,19.96 170.36,27.42 174.01,27.42 174.47,26.95 187.42,26.95 193.2,32.73 v1(194.67,32.73)
  BOTTOM w0.102: R9.2 163.91,16.96 v1(163.36,16.41) 163.15,16.62 R210.1
DDR3_VCCA_PWROK: length 36.4
  TOP w0.102: U1.AV26 190.29,62.02 v1(190.64,61.66)
  LAY3 w0.102: v1(194.38,34.84) 194.38,38.57 197.69,41.88 197.69,55.92 195.19,58.41 195.19,59.3 194.18,60.31 193.11,60.31 192.22,61.2 191.1,61.2 v1(190.64,61.66)
  BOTTOM w0.102: v1(194.38,34.84) 194.38,33.65 194.75,33.28 R214.2 R588.1
DDR3L_DRAMRST#: length 45.9
  TOP w0.102: U1.BA42 192.04,70.26 v1(192.04,70.42)
  TOP w0.127: CN1.30 v1(218.59,92.65)
  LAY4 w0.102: 193.44,77.66 193.44,75.63 192.14,74.34 192.14,70.53 v1(192.04,70.42)
  LAY4 w0.127: v1(218.59,92.65) 219.35,91.89 219.35,86.43 218.84,85.92 210.71,85.92 204.61,79.82 195.6,79.82 193.44,77.66
DDR3L_EVENT: length 264
  LAY3 w0.102: v1(50.58,37) 50.58,38.99 48.95,40.61 48.95,55.92 48.12,56.74 48.12,58.32 48.52,58.72 v1(48.65,58.72)
  LAY4 w0.102: v1(223.17,42.11) 218.4,37.33 215.38,37.33 214.71,36.66 214.71,34.97 208.59,28.84 202.45,28.84 200.08,26.47 200.08,15.05 196.71,11.68 193.94,11.68 193.42,11.16 183.2,11.16 181.08,13.28 173.05,13.28 170.65,10.88 154.94,10.88 152.89,12.93 152.47,12.93 151.44,13.96 145.75,13.96 143.25,11.45 141.48,11.45 140.87,12.05 130.52,12.05 127.46,15.11 110.58,15.11 106.68,19.01 106.68,46.11 104.79,47.99 98.02,47.99 88.01,37.98 70.05,37.98 68.22,36.15 58.91,36.15 57.69,37.38 50.96,37.38 v1(50.58,37)
  BOTTOM w0.102: v1(223.17,42.11) 219.71,42.11 219.35,41.74 R149.1 ; U31.68 47.31,59.06 47.65,58.72 v1(48.65,58.72)
DP_HPD: length 28.6
  TOP w0.102: v1(173.89,85.36) 173.41,84.88 R19.2 173.41,84.13 Q4.1
  LAY3 w0.102: v1(173.89,85.36) 173.79,85.46 173.79,89.48 168.02,95.25 155.76,95.25 v1(155.27,94.77)
  BOTTOM w0.102: U16.11 v1(155.27,94.77)
DRVH1: length 8.5
  TOP w0.178: U11.33 164.94,18.79 165.1,18.63
  TOP w0.635: R204.1 171.46,16.27 167.46,16.27 165.1,18.63
DRVH1_5614561: length 1.7
  TOP w0.635: Q9.1 v2(129.12,67.98)
  BOTTOM w0.635: R189.1 129.12,67.04 v2(129.12,67.98)
DRVH1_R: length 1.6
  TOP w0.635: R204.2 Q15.1
DRVH1_R_5614085: length 8.6
  BOTTOM w0.305: U10.16 122.84,62.56 123.45,63.18
  BOTTOM w0.635: R189.2 124.38,65.53 123.45,64.6 123.45,63.18
DRVH2: length 18
  TOP w0.178: v2(155.96,24.73) 156.31,24.73 156.65,24.39 U11.3
  TOP w0.635: R201.2 v2(151.37,38.62)
  LAY3 w0.635: v2(155.96,24.73) 154.87,25.82 154.87,34.31 151.37,37.8 v2(151.37,38.62)
DRVH2_5615145: length 1.5
  TOP w0.635: Q10.8 R190.2
DRVH2_R: length 1.5
  TOP w0.635: Q14.1 153.78,38.62 R201.1
DRVH2_R_5614085: length 8.2
  TOP w0.635: R190.1 118.16,67.89 119.26,66.79 119.26,63.27 v2(119.37,63.16)
  BOTTOM w0.305: U10.10 119.8,62.74 v2(119.37,63.16)
DRVH6: length 29.1
  TOP w0.178: U11.43 165.7,23.19 165.85,23.04 166.28,23.04 166.41,23.16
  TOP w0.381: 166.41,23.16 167.23,23.99
  TOP w0.635: 167.23,23.99 168.59,23.99 v2(169.48,23.1) ; R197.2 v2(190.74,20.54)
  LAY3 w0.635: v2(190.74,20.54) 183.97,20.54 183.47,20.04 172.54,20.04 v2(169.48,23.1)
DRVH6_R: length 1.8
  TOP w0.508: Q13.8 191.76,22.07 R197.1
DRVL1: length 9.1
  TOP w0.178: U11.37 166.08,20.79
  TOP w0.203: 166.08,20.79 166.42,20.45
  TOP w0.508: 166.42,20.45 167.23,19.63
  TOP w0.635: 167.23,19.63 170.29,19.63 171.37,20.72 R205.1
DRVL1_5614359: length 1.8
  TOP w0.635: R191.1 129.12,59.83 Q9.6
DRVL1_R: length 1.9
  TOP w0.635: R205.2 173.08,22.22 Q15.6
DRVL1_R_5614085: length 8.5
  TOP w0.635: v2(122.6,63.54) 122.6,61.47 124.25,59.82 R191.2
  BOTTOM w0.254: v2(122.6,63.54) 122.22,63.16 U10.15
DRVL2: length 9.9
  TOP w0.178: v2(155.32,23.2) 155.68,22.85 156.15,22.85 156.21,22.79 U11.7
  TOP w0.635: v2(152.66,28.55) 152.68,28.57 R202.2
  LAY3 w0.635: v2(155.32,23.2) 154.82,23.2 152.66,25.36 v2(152.66,28.55)
DRVL2_5615173: length 2.6
  TOP w0.635: Q10.3 v2(123.23,74.1)
  BOTTOM w0.762: v2(123.23,74.1) 123.07,73.94 R192.2
DRVL2_R: length 1.5
  TOP w0.635: Q14.6 153.78,31.58 R202.1
DRVL2_R_5614085: length 12.6
  BOTTOM w0.305: U10.11 120.4,63.39 120,63.79
  BOTTOM w0.635: R192.1 120.59,73 118.38,70.8 118.38,65.41 120,63.79
DRVL6: length 36
  TOP w0.178: U11.39 165.48,21.59
  TOP w0.203: 165.48,21.59 165.57,21.67
  TOP w0.406: 165.57,21.67 166.77,21.67 v2(166.88,21.56)
  TOP w0.635: R199.2 195.78,13.59 v2(195.95,13.42)
  LAY3 w0.635: v2(166.88,21.56) 167.59,21.56 171.55,17.6 182.79,17.6 183.31,17.08 192.29,17.08 v2(195.95,13.42)
DRVL6_R: length 3.2
  TOP w0.508: 196.06,15.58 Q13.3
  TOP w0.635: 196.06,15.58 196.06,15.56 195.59,15.09 R199.1
EC_BLEN: length 111.9
  LAY3 w0.102: v1(143.76,79.82) 143.52,80.05 123.06,80.05 121.48,81.63 115.43,81.63 115.02,82.04 105.45,82.04 103.5,80.09 102.05,80.09 99.7,77.74 89.1,77.74 86.95,79.88 68.81,79.88 61.2,72.28 61.2,57.35 v1(59.23,55.38)
  BOTTOM w0.102: v1(143.76,79.82) 143.75,79.82 143.75,83.49 R543.1
  BOTTOM w0.114: U31.35 59.53,55.67 v1(59.23,55.38)
EC_IRQB: length 14.4
  TOP w0.102: v1(66.32,63.73) 66.98,63.07 72.94,63.07 74.27,61.74 74.68,61.74 75.76,62.81 76.01,62.81 v1(76.06,62.86) 76.21,62.71 R407.1
  BOTTOM w0.102: U32.8 76.36,63.16 v1(76.06,62.86)
  BOTTOM w0.114: R562.2 65.97,63.38 v1(66.32,63.73)
EC_MUTE#: length 46
  LAY3 w0.102: v1(58.84,38.27) 58.84,56 60.19,57.35 60.19,59.35 v1(60.29,59.45)
  BOTTOM w0.102: R350.2 38.05,38.03 38.29,38.27 v1(58.84,38.27)
  BOTTOM w0.114: U31.28 60.31,59.46 v1(60.29,59.45) ; U26.1 37.64,36.73 38.05,37.15 R350.2
EDID_SCL: length 14.4
  TOP w0.102: U17.6 138.64,96.57 R270.1 138.39,96.03 138.73,95.69 143.59,95.69 145.69,93.59 148.18,93.59 v1(148.76,93.01)
  BOTTOM w0.102: v1(148.76,93.01) 148.76,93.4 148.92,93.57 U16.29
EDID_SDA: length 15.4
  TOP w0.102: v1(148.1,93.03) 145.73,93.03 143.5,95.27 138.32,95.27 137.57,96.02 R271.1 137.37,96.52 U17.5
  BOTTOM w0.102: U16.30 148.66,93.97 148.1,93.41 v1(148.1,93.03)
EDP_AUXN: length 40.9
  TOP w0.101: v1(176.12,70.43) 176.33,70.22 U1.K42
  LAY3 w0.112: v1(173.22,80.15) 173.05,80.32 173.05,82.94 164.92,91.07 164.92,91.7 v1(165.45,92.23)
  LAY4 w0.089: v1(176.12,70.43) 176.33,70.22 176.33,70.12 176.24,70.03 175.94,70.03 175.31,70.66 175.31,71.61 174.38,72.54 174.38,72.9
  LAY4 w0.112: v1(173.22,80.15) 173.22,79.32 173.53,79.01 173.53,77.25 173.16,76.88 173.16,75.67 174.38,74.45 174.38,72.9
  BOTTOM w0.124: C299.2 159.12,100.06 159.63,99.54 162.33,99.54 164.93,96.94 164.93,92.75 v1(165.45,92.23)
EDP_AUXP: length 40.9
  TOP w0.101: v1(176.8,70.42) 177,70.23 U1.M42
  LAY3 w0.112: v1(164.68,92.23) 164.68,90.97 172.81,82.84 172.81,80.5 v1(172.46,80.15)
  LAY4 w0.089: v1(176.8,70.42) 176.55,70.17 176.55,70.03 176.33,69.81 175.85,69.81 175.09,70.57 175.09,71.52 174.14,72.48 174.14,72.9
  LAY4 w0.112: v1(172.46,80.15) 172.98,79.63 172.98,79.22 173.29,78.91 173.29,77.35 172.92,76.98 172.92,75.57 174.14,74.35 174.14,72.9
  BOTTOM w0.124: C303.2 162.23,99.29 164.68,96.84 v1(164.68,92.23)
EDP_BKLCTL: length 97.2
  TOP w0.114: U1.P52 178.29,75.07 178.29,76.54 v1(177.94,76.89)
  LAY3 w0.102: v1(98.4,91.77) 110.67,91.77 111.35,92.44 117.01,92.44 119.77,95.21 148.67,95.21 149.98,93.89 152.55,93.89 153.47,92.97 154.98,92.97 155.52,93.51 165.79,93.51 167.98,91.32 167.98,89.15 v1(174.55,82.59)
  BOTTOM w0.089: 176.44,78.93 176.52,78.85 176.52,77.48 177.11,76.89 v1(177.94,76.89)
  BOTTOM w0.102: 176.44,78.93 175.96,79.4 175.64,79.4 174.99,80.06 174.99,80.66 174.55,81.1 v1(174.55,82.59)
  BOTTOM w0.203: v1(98.4,91.77) 97.61,90.98 R538.1 96.97,90.99 Q49.1
EDP_BKLCTL_3P3: length 69
  TOP w0.203: R259.1 147.72,101.19 v1(146.6,100.07)
  LAY3 w0.203: v1(146.6,100.07) 146.12,99.59 135,99.59 134.74,99.84 107.91,99.84 105.66,97.6 103.19,97.6 v1(101.59,96)
  BOTTOM w0.203: v1(101.59,96) 103.3,94.3 Q48.3 104.27,93.08 R536.2 107.94,92.65 108.2,92.91 110.43,92.91 110.92,92.42 115.4,92.42 116.43,91.39 116.43,90.53 116.75,90.21 R534.2
EDP_BKLEN: length 39.4
  TOP w0.102: 178.53,75.63 178.53,75.26 178.61,75.18 178.61,74.9 178.33,74.61 178.33,74.34 U1.P51 ; v1(162.54,85.18) 162.74,85.37 168.95,85.37 172.38,81.95 173.73,81.95 175.05,80.63 175.05,80.42 177.94,77.52
  TOP w0.114: 178.53,75.63 178.53,76.94 177.94,77.52
  BOTTOM w0.102: v1(162.54,85.18) 161.93,85.18 157.23,80.48 150.75,80.48 150.35,80.08 R544.1
  BOTTOM w0.203: Q51.1 149.08,80.09 R544.1
EDP_BKLEN_3P3: length 4.6
  BOTTOM w0.203: Q50.3 148.27,88.7 147.44,87.87 R539.2 R542.1 146.86,87.01 U42.1
EDP_BKLEN_OUT: length 52.8
  LAY3 w0.203: v1(144.95,85.12) 144.64,85.12 142.51,87.25 140.73,87.25 140.4,86.92 136.94,86.92 135.86,87.99 133.2,87.99 132.36,87.16 128.73,87.16 128.03,86.46 125.63,86.46 124.49,87.6 114.83,87.6 113.88,86.66 108.96,86.66 v1(108.8,86.82)
  BOTTOM w0.203: v1(108.8,86.82) 108.96,86.66 111.92,86.66 115.89,82.69 R3094.1 ; v1(144.95,85.12) 144.95,84.99 R541.2 R543.2 143.69,84.51 U42.4
EDP_TXN0: length 36.3
  TOP w0.089: 173.43,78.52 173.34,78.43 173.34,77.95 173.25,77.86 173.02,77.86 v1(172.86,78.02)
  TOP w0.101: 173.43,78.52 174.42,78.52 175.38,77.56 175.38,75.05 175.57,74.86 175.57,74.77 175.58,74.76 175.58,74.67 175.45,74.54 U1.H51
  LAY3 w0.112: v1(163.36,91.53) 163.36,89.91 164.31,88.96 165.59,88.96 171.13,83.42 171.13,81.73 171.38,81.47 171.78,81.47 171.89,81.36 171.89,81.14 171.78,81.03 171.38,81.03 171.13,80.78 171.13,78.93 171.81,78.25 172.63,78.25 v1(172.86,78.02)
  BOTTOM w0.124: C281.1 159.13,97.73 161.71,97.73 163.36,96.07 v1(163.36,91.53)
EDP_TXN1: length 38.4
  TOP w0.101: v1(176.06,78.08) 176.06,77.86 176.2,77.72 176.45,77.72 176.68,77.49 176.68,76.27 176.39,75.98 176.39,75.05 U1.K52
  LAY3 w0.112: v1(176.06,78.08) 176.37,77.77 176.77,77.77 177.28,77.26 177.28,76.44 176.71,75.86 175.13,75.86 173.94,77.05 171.5,77.05 170.07,78.49 170.07,83.34 165.35,88.06 163.8,88.06 162.14,89.72 v1(162.14,90.65)
  BOTTOM w0.124: v1(162.14,90.65) 162.14,94.73 161.59,95.27 159.21,95.27 C290.1
EDP_TXP0: length 36.3
  TOP w0.101: v1(172.86,78.75) 174.51,78.75 175.61,77.65 175.61,75.15 175.8,74.96 175.8,74.77 U1.J51
  LAY3 w0.112: v1(164.14,91.53) 163.6,90.99 163.6,90.01 164.41,89.2 165.69,89.2 171.37,83.52 171.37,81.83 171.48,81.71 171.88,81.71 172.13,81.46 172.13,81.04 171.88,80.79 171.48,80.79 171.37,80.68 171.37,79.03 171.91,78.49 172.6,78.49 v1(172.86,78.75)
  BOTTOM w0.124: v1(164.14,91.53) 163.75,91.91 163.74,91.91 163.62,92.04 163.62,96.18 161.81,97.98 159.28,97.98 C287.1
EDP_TXP1: length 38.5
  TOP w0.101: U1.K51 176.38,74.62 176.06,74.93 176.06,75.15 176.17,75.26 176.17,76.07 176.46,76.36 176.46,77.4 176.36,77.5 176.22,77.5 v1(176.06,77.34)
  LAY3 w0.112: v1(176.06,77.34) 176.24,77.53 176.67,77.53 177.04,77.16 177.04,76.53 176.61,76.1 175.23,76.1 174.04,77.29 171.6,77.29 170.31,78.58 170.31,83.44 165.45,88.3 163.9,88.3 162.37,89.82 162.37,90.28 162.49,90.39 162.64,90.39 v1(162.91,90.65)
  BOTTOM w0.124: v1(162.91,90.65) 162.39,91.18 162.39,94.83 161.69,95.53 159.21,95.53 C292.2
EDP_VDDEN: length 66.3
  TOP w0.102: v1(162.12,83.09) 162.12,85.43 162.32,85.62 169.1,85.62 172.48,82.24 173.79,82.24 175.42,80.61 175.42,80.5 177.61,78.31 177.93,78.31 ; 178.81,76.75 U1.R53 ; v1(127.47,87.8) 127,87.8 126.54,87.34 Q31.1
  TOP w0.114: 178.81,76.75 178.81,77.43 177.93,78.31
  LAY3 w0.102: v1(127.47,87.8) 127.47,88.41 129.29,90.22 136.89,90.22 137.64,89.47 146.65,89.47 149.51,86.62 155.53,86.62 159.05,83.09 v1(162.12,83.09)
EECS: length 2.4
  BOTTOM w0.114: R300.2 125.5,38.09 124.79,38.8 U22.30
EEDI: length 2.4
  BOTTOM w0.114: U22.32 124.83,38 125.63,37.21 R298.2
EMMC_CLK: length 25.4
  TOP w0.102: v1(176.93,52.52) 177.27,52.86 U1.M7
  LAY3 w0.127: v1(183.88,38.48) 179.85,38.48 179.28,39.05 179.28,40.01 179.06,40.24 178.63,40.24 176.38,42.49 176.38,47.74 176.73,48.1 176.73,48.61 175.44,49.9 175.44,51.28 176.68,52.52 v1(176.93,52.52)
  BOTTOM w0.114: v1(183.88,38.48) 184.28,38.48 185.89,36.87 185.89,36.68 185.65,36.44 R167.1
EMMC_CMD: length 25.5
  TOP w0.114: U1.P6 178.07,51.88 v1(177.82,51.88)
  LAY3 w0.127: v1(181.73,41.05) 181.73,39.65 181.61,39.52 181.33,39.52 181.2,39.66 181.2,40.32 181.07,40.45 180.62,40.45 180.34,40.73 180.34,41.53 180.08,41.78 178.88,41.78 178.01,42.66 178.01,50.42 177.36,51.07 177.36,51.42 v1(177.82,51.88)
  BOTTOM w0.102: 183.66,38.99 183.06,39.58 182.51,39.58
  BOTTOM w0.114: v1(181.73,41.05) 181.73,40.36 182.51,39.58 ; R165.1 186.54,36.99 184.54,38.99 183.66,38.99
EMMC_DATA_0: length 25.4
  TOP w0.102: U1.M6 177.17,52.14 v1(176.9,51.88)
  LAY3 w0.127: v1(180.5,40.02) 180.79,39.72 180.79,39.14 180.66,39.01 180.09,39.01 179.81,39.29 179.81,40.57 179.61,40.76 178.82,40.76 177.23,42.35 177.23,43.31 177.06,43.48 176.89,43.65 176.89,44.16 177.06,44.33 177.23,44.5 177.23,45.01 177.06,45.18 176.89,45.35 176.89,45.86 177.06,46.02 177.23,46.19 177.23,46.7 177.06,46.87 176.89,47.04 176.89,47.55 177.06,47.72 177.23,47.89 177.23,49.85 176.41,50.67 176.41,51.38 v1(176.9,51.88)
  BOTTOM w0.114: v1(180.5,40.02) 180.5,39.36 180.62,39.25 181.15,39.25 181.26,39.14 181.26,38.91 181.15,38.79 180.59,38.79 180.48,38.68 180.48,38.45 180.6,38.34 181.15,38.34 181.26,38.22 181.26,37.99 181.15,37.88 180.62,37.88 180.5,37.76 180.5,37.46 179.9,36.86 179.9,36.64 179.78,36.52 179.56,36.52 179.43,36.38 R158.1
EMMC_DATA_1: length 23
  TOP w0.102: U1.M4 177.15,51.47 v1(176.89,51.22)
  LAY3 w0.127: v1(179.69,41.24) 178.89,41.24 177.62,42.51 177.62,50.22 176.89,50.94 v1(176.89,51.22)
  BOTTOM w0.114: v1(179.69,41.24) 179.83,41.24 179.97,41.38 179.97,41.75 179.79,41.93 179.22,41.93 179.1,41.81 179.1,40.68 179.21,40.56 179.58,40.56 179.69,40.45 179.69,37.77 179.12,37.2 178.76,37.2 178.64,37.08 178.64,36.72 178.53,36.6 178.3,36.6 178.18,36.72 178.18,37.08 178.07,37.19 177.84,37.19 177.31,36.67 177.31,36.3 R164.1
EMMC_DATA_2: length 22.8
  TOP w0.102: U1.P9 178.11,53.57 v1(177.82,53.28)
  LAY3 w0.114: v1(179.09,42.76) 178.85,43 178.85,45.63
  LAY3 w0.127: v1(177.82,53.28) 178.2,53.66 178.33,53.66 178.44,53.54 178.44,51.55 178.94,51.05 178.94,49.91 179.35,49.5 179.35,48.68 178.85,48.18 178.85,45.63
  BOTTOM w0.114: R157.1 175.87,36.29 177.61,38.03 177.61,38.31 177.75,38.45 177.9,38.45 178.03,38.58 178.03,38.93 177.92,39.04 177.72,39.04 177.61,39.15 177.61,39.38 177.72,39.5 177.88,39.5 178.02,39.63 178.02,39.85 178.26,40.09 178.26,40.95 178.12,41.09 177.75,41.09 177.63,41.2 177.63,41.43 177.75,41.54 178.22,41.54 178.35,41.67 178.35,42.13 178.97,42.76 v1(179.09,42.76)
EMMC_DATA_3: length 27.6
  TOP w0.114: U1.P7 177.99,52.52 v1(177.82,52.52)
  LAY3 w0.127: v1(181.33,42.24) 181.33,43.19 181.46,43.32 181.76,43.32 181.89,43.2 181.89,41.69 181.73,41.53 181.43,41.53 181.28,41.38 181.28,41.06 181.12,40.91 180.86,40.91 180.74,41.04 180.74,42.07 180.56,42.24 180.1,42.24 179.98,42.37 179.98,42.51 179.85,42.64 179.6,42.64 179.47,42.51 179.47,42.37 179.34,42.24 178.96,42.24 178.47,42.74 178.47,51.01 178.21,51.27 178.21,52.13 v1(177.82,52.52)
  BOTTOM w0.114: v1(181.33,42.24) 181.68,42.24 181.77,42.15 181.77,41.74 181.64,41.61 181.43,41.61 181.27,41.46 181.27,40.84 181.35,40.76 181.35,40.18 182.05,39.47 182.05,37.16 181.88,36.98 181.39,36.98 181.21,36.8 R162.1
EMMC_DATA_4: length 26.4
  TOP w0.102: v1(178.83,52.52) 179.21,52.14 U1.T6
  LAY3 w0.127: v1(180.53,42.74) 180.29,42.74 180.16,42.87 180.16,43.26 180.03,43.39 179.36,43.39 179.23,43.52 179.23,43.76 179.37,43.9 179.98,43.9 180.1,44.02 180.1,44.28 179.98,44.4 179.36,44.4 179.23,44.53 179.23,44.78 179.37,44.91 179.98,44.91 180.1,45.04 180.1,45.29 179.98,45.42 179.36,45.42 179.23,45.55 179.23,45.8 179.37,45.93 179.98,45.93 180.1,46.06 180.1,46.31 179.98,46.44 179.36,46.44 179.23,46.56 179.23,46.81 179.37,46.94 179.98,46.94 180.1,47.07 180.1,48.75 179.98,48.88 179.79,48.88 179.66,49 179.66,49.26 179.79,49.38 179.98,49.38 180.1,49.51 180.1,49.98 179.38,50.71 179.38,52.63 179.25,52.76 178.98,52.76 178.83,52.61 v1(178.83,52.52)
  BOTTOM w0.114: v1(180.53,42.74) 180.53,42.38 180.82,42.09 180.82,40.74 180.93,40.64 180.93,40.05 181.65,39.32 181.65,37.57 181.46,37.38 180.96,37.38 180.32,36.73 R160.1
EMMC_DATA_5: length 23.4
  TOP w0.102: v1(178.83,53.15) 179.13,52.86 U1.T7
  LAY3 w0.127: v1(180.89,43.31) 180.65,43.31 180.48,43.48 180.48,44.48 180.61,44.6 180.94,44.6 181.07,44.73 181.07,44.99 180.94,45.11 180.61,45.11 180.48,45.24 180.48,45.49 180.61,45.62 180.94,45.62 181.07,45.75 181.07,46 180.94,46.13 180.61,46.13 180.48,46.26 180.48,49.98 179.66,50.81 179.66,53.08 179.3,53.44 179.12,53.44 v1(178.83,53.15)
  BOTTOM w0.114: R161.1 178.54,36.08 180.09,37.63 180.09,40.74 180.17,40.82 180.36,40.82 180.45,40.91 180.45,41.85 179.96,42.34 179.96,43.12 180.45,43.61 180.75,43.61 180.89,43.48 v1(180.89,43.31)
EMMC_DATA_6: length 24
  TOP w0.102: v1(178.83,53.91) 179.2,54.28 U1.T10
  LAY3 w0.127: v1(181.39,43.98) 181.45,44.05 181.45,49.43 179.91,50.97 179.91,53.23 179.23,53.91 v1(178.83,53.91)
  BOTTOM w0.114: v1(181.39,43.98) 180.3,43.98 179.59,43.27 179.59,42.49 179.43,42.32 179.06,42.32 178.72,41.98 178.72,40.35 178.92,40.15 179.2,40.15 179.31,40.03 179.31,38.03 178.87,37.59 177.69,37.59 176.76,36.66 R159.1
EMMC_DATA_7: length 25.4
  TOP w0.102: v1(178.83,54.68) 179.15,54.99 U1.T12
  LAY3 w0.127: v1(178.83,54.68) 180.23,53.28 180.23,51.26 183.06,48.42 183.06,46.13 182,45.06 v1(182,44.94)
  BOTTOM w0.114: v1(182,44.94) 180.61,44.94 177.07,41.4 177.07,40.26 177.24,40.09 177.24,38.22 R156.1
EMMC_RESET: length 0.9
  BOTTOM w0.114: R166.2 184.1,36.19 R168.1
ENA: length 0.9
  BOTTOM w0.203: U41.9 118.89,83.6 118.89,82.69 R3094.2
ENBLT: length 13
  LAY4 w0.102: v1(146.32,85.15) 146.32,86.56 v1(151.76,92)
  BOTTOM w0.102: v1(146.32,85.15) 146.32,84.27 145.61,83.56 R541.1 ; v1(151.76,92) 151.91,92.15 U16.23
ENPVCC/I2C_ADDR: length 1.4
  TOP w0.305: R272.1 149.82,95.16 v1(149.83,95.17)
  BOTTOM w0.102: U16.33 v1(149.83,95.17)
ENSWREG: length 7.4
  BOTTOM w0.178: U22.33 124.6,37.6 125.63,36.57
  BOTTOM w0.381: 125.63,36.57 127.91,36.57 128.43,37.09 R303.1 R302.2
EVDD10: length 2.3
  BOTTOM w0.178: U22.21 121.93,42.52 122.45,43.05 122.45,43.56
FAN_BACK: length 4.5
  TOP w0.203: R2.2 R3.2 ; R3.2 134.88,12.15 CN25.2 ; R3.2 134.39,12.15 134,11.77 D28.P
FAN_PWMIN: length 113.6
  TOP w0.102: CN25.3 137.86,11.15 138.08,11.36 138.08,13.72 v1(137.07,14.72)
  LAY4 w0.102: v1(65.25,53.85) 66.9,52.2 94.43,52.2 97.05,49.58 105.87,49.58 107.93,47.52 107.93,40.01 108.87,39.08 108.87,36.06 109.83,35.1 111.41,35.1 119.39,27.11 119.39,18.33 121.39,16.33 127.11,16.33 128.76,14.68 137.03,14.68 v1(137.07,14.72)
  BOTTOM w0.102: U31.24 62.7,61.06 63.94,59.82 R258.1 63.94,55.15 v1(65.25,53.85)
FAN_VCC: length 3.1
  TOP w0.508: FB24.1 134.19,14.07 C565.2 136.18,13.15 CN25.1
FB3: length 39
  TOP w0.178: U11.12 156.69,20.79 156.51,20.6 156.51,20.47 155.42,19.39 155.2,19.39
  TOP w0.254: v1(149.61,19.54) 149.77,19.39 155.2,19.39
  BOTTOM w0.381: v1(149.61,19.54) 149.61,22.5 152.08,24.97 152.08,26.78 156.62,31.32 161.78,31.32 165.62,35.16 165.62,37.97 166.63,38.97 R821.1 R109.2
FB4: length 22.3
  TOP w0.178: U11.23 160.44,15.17 v1(160.53,15.07)
  LAY4 w0.203: v1(148.97,16.77) 149.49,16.25 151.54,16.25 152.54,17.25 152.54,17.98 153.11,18.55 154.05,18.55 154.71,17.89 159.96,17.89 160.4,17.45 160.4,15.21 v1(160.53,15.07)
  BOTTOM w0.203: C823.2 148.69,15.89 148.97,16.17 v1(148.97,16.77) ; C823.2 R842.1 ; C823.2 R843.2
FB5: length 16.4
  TOP w0.178: v1(159.89,15.07) 160.11,15.29 160.11,17.54 160.04,17.61 U11.22
  LAY4 w0.203: v1(159.89,15.07) 159.13,15.83 159.13,17.08 158.63,17.58 154.88,17.58 153.62,16.33 152.11,16.33 151.55,15.77 v1(150.37,15.77)
  BOTTOM w0.203: R844.2 150.37,15.25 v1(150.37,15.77)
FBGND2: length 5.1
  TOP w0.203: U11.1 157.02,25.19 156.81,25.39 156.81,28.5 R826.2
  TOP w0.254: R826.2 156.36,29.71 R827.2
FBVOUT1: length 67.4
  TOP w0.178: v1(163.36,17) 163.36,17.18 162.84,17.71 U11.29
  LAY3 w0.305: v1(169.8,24.02) 169.9,24.02 172.26,21.66 190.66,21.66 191.02,22.02 v1(200.86,22.02)
  BOTTOM w0.203: R823.1 R563.1 196.11,38.13 201.99,32.25 201.99,23.15 v1(200.86,22.02)
  BOTTOM w0.305: v1(163.36,17) 163.82,17.46 167.51,17.46 170.57,20.52 170.57,23.24 v1(169.8,24.02)
FBVOUT2: length 6.5
  TOP w0.178: U11.2 156.76,24.79 156.43,25.12
  TOP w0.254: R825.1 155.69,27.88 R105.2 155.04,27.23 155.04,26.28 155.81,25.51 156.04,25.51 156.43,25.12
FLASH_TXE: length 163.1
  LAY3 w0.102: v1(45.3,78.29) 45.3,71.92 42.33,68.95 42.33,66.21 v1(42.58,65.96) ; v1(173.03,95.15) 170.53,97.65 157.04,97.65 156.42,97.02 150.31,97.02 149.46,96.17 118.72,96.17 115.95,93.4 108.62,93.4 108.32,93.11 98.38,93.11 96.53,94.97 85.77,94.97 84.49,96.25 56.14,96.25 v1(54.71,97.68)
  LAY4 w0.102: v1(45.3,78.29) 45.37,78.29 52.48,85.4 52.48,95.45 v1(54.71,97.68)
  BOTTOM w0.102: R397.2 42.59,65.97 v1(42.58,65.96) ; v1(173.03,95.15) 173.71,94.48 Q5.1
FMISO: length 15.6
  TOP w0.102: U34.2 48.28,71.35 48.14,71.2 47.5,71.2 47.37,71.07 47.37,70.79 47.27,70.69 46.54,70.69 46.44,70.59 46.44,70.38 46.54,70.28 47.27,70.28 47.37,70.18 47.37,69.92 47.24,69.79 46.61,69.79 46.54,69.72 46.54,69.42 46.64,69.31 48.51,69.31 48.68,69.49 48.68,70.98 48.84,71.14 49.8,71.14 49.9,71.04 49.9,70.09 50.09,69.9 v1(51.08,69.9)
  BOTTOM w0.114: v1(51.08,69.9) 50.33,70.65 U31.103
FMOSI: length 15.6
  TOP w0.102: v1(49.43,69.9) 49.43,69.67 49.77,69.34 51.62,69.34 52.04,69.76 52.04,73.91 51.35,74.6 51.35,77.56 50.82,78.08 U34.5
  BOTTOM w0.114: U31.102 49.93,70.4 v1(49.43,69.9)
FSCE#: length 15.7
  TOP w0.102: v1(49.43,70.54) 49.11,70.54 49,70.43 49,69.04 48.9,68.94 48.44,68.94 48.34,68.84 48.34,68.66 48.24,68.56 48.04,68.56 47.93,68.66 47.93,68.84 47.83,68.94 47.24,68.94 47.14,68.84 47.14,68.04 47.04,67.94 46.86,67.94 46.73,68.06 46.73,68.84 46.63,68.94 46.3,68.94 46.06,69.18 45.49,69.18 45.39,69.29 45.39,69.48 45.5,69.59 46.06,69.59 46.16,69.69 46.16,69.99 46.04,70.11 45.64,70.11 45.54,70.21 45.54,70.41 45.64,70.51 46.07,70.51 46.17,70.61 46.17,70.82 46.07,70.92 45.74,70.92 45.64,71.02 45.64,71.22 45.74,71.32 46.9,71.32 47.01,71.44 U34.1
  BOTTOM w0.114: v1(49.43,70.54) 49.53,70.64 U31.101
FSCK: length 15.7
  TOP w0.102: U34.6 49.55,79.08 50.41,78.22 50.41,77.66 50.31,77.56 49.82,77.56 49.72,77.46 49.72,77.26 49.82,77.16 50.31,77.16 50.41,77.05 50.41,76.85 50.31,76.75 49.82,76.75 49.72,76.65 49.72,76.44 49.82,76.34 50.31,76.34 50.41,76.24 50.41,75.16 51.71,73.86 51.71,71.37 51.59,71.25 50.35,71.25 50.25,71.15 50.25,70.66 50.37,70.53 51.12,70.53 v1(51.13,70.54)
  BOTTOM w0.114: U31.105 v1(51.13,70.54)
GA20_EC: length 21
  TOP w0.114: v1(59.53,70.54) 60.41,70.54 61.05,69.9 v1(70.13,69.9)
  BOTTOM w0.114: U31.126 v1(59.53,70.54) ; R429.2 72.8,66.57 72.8,70.38 R406.2 71.89,71.28 Q42.3 v1(70.13,69.9)
GL834L_3V3: length 35.1
  TOP w0.305: 77.34,98.32 v1(74.76,98.32) ; 77.34,98.32 77.68,98.32 77.69,98.32 ; 77.34,98.32 77.69,98.67 ; 77.69,98.67 77.69,98.32 ; 77.69,98.67 v1(77.69,100.7) 77.07,101.31 74.05,101.31 v1(73.16,100.42) 73.16,99.59 71.86,98.28 v1(70.94,98.28) ; 77.69,98.32 79.61,96.39 v1(79.61,91.61)
  BOTTOM w0.203: U95.1 76.66,95.87 76.99,96.21 C701.1
  BOTTOM w0.254: U95.19 72.77,96.95 72.33,97.39 71.92,97.39 71.54,97.78 C705.1 ; C710.2 75.26,97.92 74.77,97.43 U95.23
  BOTTOM w0.305: C701.1 77.7,97.21 C708.1 C700.1 77.7,99.87 FB19.1 v1(77.69,100.7) ; R801.1 v1(73.16,100.42) ; C705.1 v1(70.94,98.28) ; FB20.2 v1(79.61,91.61) ; C710.2 v1(74.76,98.32)
GL850_AVDD: length 23.1
  TOP w0.305: U9.1 180.61,86.18 C147.2 ; 179.83,92.03 U9.10 ; C151.2 180.44,87.87 v1(180.1,88.21) 179.53,88.78 U9.5
  TOP w0.381: 179.83,92.03 180,92.2 C152.2 C148.2 182,92.2 182.19,92.39 v1(182.57,92.39) ; v1(180.12,85.45) C146.2 C147.2 ; v1(184.96,94.16) 184.94,94.14 C150.2 184.19,94.28 FB1.1
  BOTTOM w0.381: v1(180.12,85.45) 180.14,85.47 180.14,88.18 v1(180.1,88.21) 180.1,88.8 182.57,91.27 v1(182.57,92.39) 184.34,94.16 v1(184.96,94.16)
GL850G_RST#: length 3.8
  TOP w0.102: R174.2 C153.2 180.71,93.95 R176.2 180.68,93.98 U9.13
